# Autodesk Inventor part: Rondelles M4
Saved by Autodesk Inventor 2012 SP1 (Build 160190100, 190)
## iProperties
Created: 2014-12
Part Number: Rondelles M4
Material: Default
Document SubType Name: Modeling
Designer: Bruno
Density: 1 g/cm^3
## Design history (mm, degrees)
node "Rondelles M41"
node "Rondelles M4"
node "Base1"
